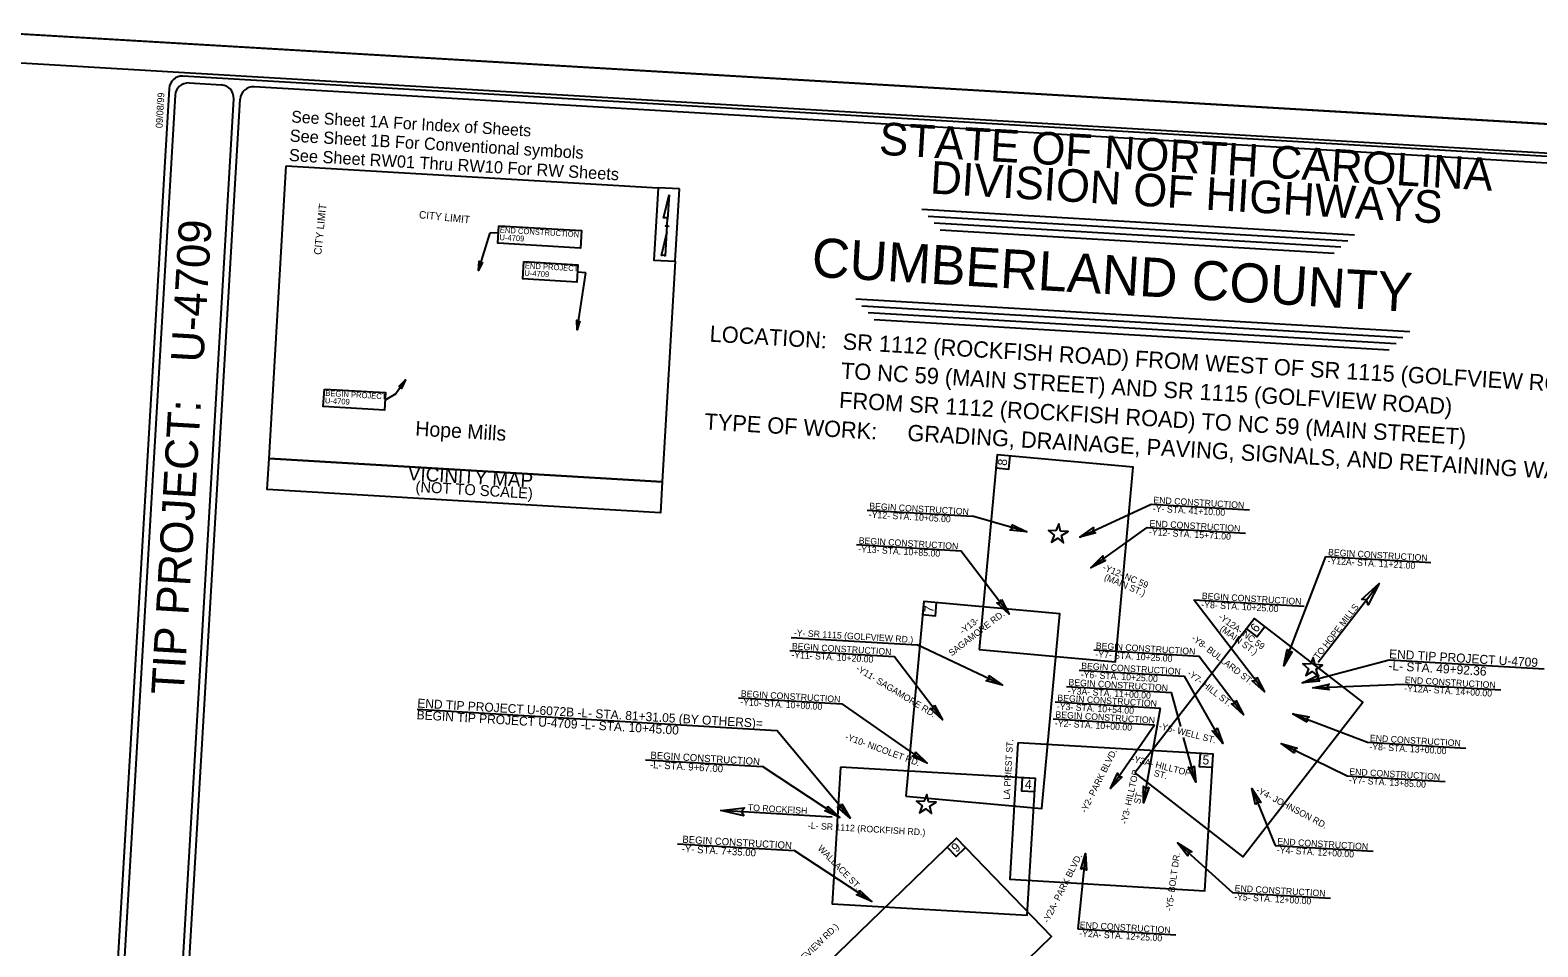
# Model space of a CAD drawing. Extents: x 1998567 to 2027801, y 439108 to 451079.
# Drawn here: x 2004989 to 2016563, y 444042 to 451079 of the extents above; entities that cross this region are included whole.
import ezdxf

# ---------------------------------------------------------------- set-up
doc = ezdxf.new("R2010")
doc.units = 0
for name, color, linetype in [('Default', 7, 'Continuous'), ('Old_Level_1', 7, 'Continuous'), ('Old_Level_12', 7, 'Continuous'), ('Old_Level_2', 7, 'Continuous'), ('Old_Level_63', 7, 'Continuous'), ('Prop Dimension', 7, 'Continuous'), ('Prop DSN Text', 7, 'Continuous'), ('Prop Grid Mask', 7, 'Continuous'), ('Prop RDY Traffic Signal CELL', 7, 'Continuous'), ('Prop Terminator CELL', 7, 'Continuous'), ('Sheet Cutting Line CELL', 7, 'Continuous'), ('Sheet Data Field CELL', 7, 'Continuous'), ('Sheet Plot Border Inside CELL', 7, 'Continuous'), ('Sheet Plot Border Outside CELL', 7, 'Continuous'), ('Sheet Title CELL', 7, 'Continuous'), ('Sheet Title Data Points CELL', 7, 'Continuous')]:
    doc.layers.add(name, color=color, linetype=linetype)

msp = doc.modelspace()

# ---------------------------------------------------------------- linework, layer by layer
at = {"layer": 'Old_Level_1'}
for points in [[(2006955, 450038), (2009810, 449870), (2009777, 449314), (2009941, 449305), (2009842, 447612), (2006823, 447790)], [(2009974, 449860), (2009810, 449870), (2009777, 449314), (2009941, 449305)], [(2012275, 446325), (2013321, 446229), (2013458, 447723), (2012413, 447819)], [(2006823, 447790), (2009842, 447612), (2009828, 447374), (2006809, 447552)], [(2011711, 445199), (2012757, 445103), (2012894, 446597), (2011849, 446693)], [(2013470, 445377), (2014300, 444733), (2015219, 445919), (2014389, 446562)], [(2012572, 445608), (2012510, 444560), (2014008, 444471), (2014070, 445520)], [(2011209, 445421), (2011147, 444373), (2012644, 444285), (2012706, 445333)], [(2011023, 443831), (2011754, 443077), (2012831, 444121), (2012100, 444875)]]:
    msp.add_lwpolyline(points, close=True, dxfattribs=at)
for points in [[(2012413, 447819), (2012403, 447719), (2012503, 447710), (2012512, 447810)], [(2011849, 446693), (2011840, 446593), (2011939, 446584), (2011948, 446684)], [(2014389, 446562), (2014328, 446483), (2014407, 446422), (2014468, 446501)], [(2014070, 445520), (2013970, 445525), (2013964, 445426), (2014064, 445420)], [(2012706, 445333), (2012606, 445339), (2012600, 445239), (2012700, 445233)], [(2012100, 444875), (2012028, 444806), (2012098, 444734), (2012170, 444803)]]:
    msp.add_lwpolyline(points, dxfattribs=at)
at = {"layer": 'Old_Level_2'}
for p, q in [((2009851, 449635), (2009894, 449815)), ((2009894, 449815), (2009883, 449627)), ((2009894, 449815), (2009894, 449815)), ((2009894, 449815), (2009894, 449815)), ((2009864, 449576), (2009896, 449574)), ((2009878, 449575), (2009864, 449576)), ((2009864, 449576), (2009864, 449576)), ((2009877, 449530), (2009883, 449633)), ((2009883, 449627), (2009883, 449633)), ((2009877, 449530), (2009833, 449346)), ((2009866, 449345), (2009877, 449530))]:
    msp.add_line(p, q, dxfattribs=at)
for centre, start_param, end_param in [((2009867, 449632), 0.216388, 2.908219), ((2009850, 449344), 0.201328, 3.141593)]:
    msp.add_ellipse(centre, major_axis=(16.6, -1.1), ratio=0.461098, start_param=start_param, end_param=end_param, dxfattribs=at)
at = {"layer": 'Old_Level_63'}
msp.add_line((2011237, 444988), (2011237, 444988), dxfattribs=at)
at = {"layer": 'Prop Dimension'}
for p, q in [((2011415, 447395), (2012223, 447347)), ((2012640, 447228), (2012223, 447347)), ((2013047, 447187), (2013596, 447440)), ((2013596, 447440), (2014349, 447396)), ((2013133, 446952), (2013565, 447261)), ((2013565, 447261), (2014318, 447217)), ((2011334, 447130), (2012135, 447082)), ((2012505, 446595), (2012135, 447082)), ((2014613, 446199), (2014936, 447039)), ((2014936, 447039), (2015743, 446992)), ((2013923, 446706), (2014769, 446657)), ((2014464, 445999), (2013923, 446706)), ((2010831, 446417), (2011798, 446360)), ((2010821, 446318), (2011622, 446271)), ((2012453, 446051), (2011798, 446360)), ((2013154, 446321), (2013962, 446274)), ((2011992, 445784), (2011622, 446271)), ((2014305, 445822), (2013962, 446274)), ((2014754, 446069), (2015423, 446245)), ((2015423, 446245), (2016613, 446175)), ((2013042, 446167), (2013850, 446120)), ((2014145, 445602), (2013850, 446120)), ((2010428, 445954), (2011223, 445908)), ((2012944, 446041), (2013752, 445993)), ((2013822, 445732), (2013752, 445993)), ((2014836, 446031), (2015525, 446059)), ((2015525, 446059), (2016279, 446015)), ((2007960, 445866), (2010722, 445703)), ((2011876, 445451), (2011223, 445908)), ((2012859, 445922), (2013667, 445874)), ((2013536, 445147), (2013667, 445874)), ((2012844, 445793), (2013621, 445747)), ((2013284, 445257), (2013621, 445747)), ((2014682, 445831), (2015257, 445613)), ((2011284, 445030), (2010722, 445703)), ((2013937, 445305), (2013844, 445649)), ((2014592, 445604), (2015100, 445355)), ((2015257, 445613), (2016010, 445568)), ((2009713, 445478), (2010611, 445425)), ((2011206, 445035), (2010611, 445425)), ((2014369, 445257), (2014547, 444820)), ((2015100, 445355), (2015853, 445311)), ((2009958, 444833), (2010855, 444780)), ((2013798, 444839), (2014220, 444460)), ((2014547, 444820), (2015300, 444775)), ((2011451, 444389), (2010855, 444780)), ((2013090, 444758), (2013031, 444179)), ((2014220, 444460), (2014973, 444416)), ((2013031, 444179), (2013784, 444134))]:
    msp.add_line(p, q, dxfattribs=at)
at = {"layer": 'Prop DSN Text'}
for p, q in [((2008430, 449233), (2008521, 449523)), ((2008584, 449520), (2008521, 449523)), ((2009189, 448778), (2009255, 449217)), ((2009255, 449217), (2009192, 449221)), ((2007871, 448396), (2007797, 448288)), ((2007797, 448288), (2007715, 448239)), ((2014877, 446226), (2015346, 446831)), ((2011147, 445038), (2010291, 445089))]:
    msp.add_line(p, q, dxfattribs=at)
at = {"layer": 'Prop Grid Mask'}
for points in [[(2008588, 449577), (2009221, 449540), (2009213, 449406), (2008580, 449443)], [(2008780, 449303), (2009195, 449278), (2009187, 449144), (2008772, 449169)], [(2007248, 448324), (2007718, 448297), (2007710, 448161), (2007240, 448189)]]:
    msp.add_lwpolyline(points, close=True, dxfattribs=at)
at = {"layer": 'Prop RDY Traffic Signal CELL'}
for points in [[(2012864, 447235), (2012806, 447239), (2012851, 447202), (2012830, 447148), (2012878, 447179), (2012923, 447143), (2012908, 447199), (2012957, 447230), (2012899, 447233), (2012885, 447289), (2012864, 447235)], [(2014817, 446211), (2014760, 446214), (2014804, 446177), (2014783, 446124), (2014832, 446155), (2014876, 446118), (2014862, 446174), (2014910, 446205), (2014853, 446209), (2014838, 446264), (2014817, 446211)], [(2011851, 445158), (2011793, 445161), (2011838, 445125), (2011817, 445071), (2011866, 445102), (2011910, 445065), (2011896, 445121), (2011944, 445152), (2011887, 445156), (2011872, 445212), (2011851, 445158)]]:
    msp.add_lwpolyline(points, dxfattribs=at)
at = {"layer": 'Prop Terminator CELL'}
for points in [[(2008462, 449299), (2008430, 449233), (2008437, 449307), (2008447, 449294)], [(2009210, 448848), (2009189, 448778), (2009185, 448852), (2009196, 448841)], [(2007820, 448343), (2007871, 448396), (2007840, 448329), (2007835, 448344)], [(2012526, 447283), (2012640, 447228), (2012513, 447241), (2012534, 447258)], [(2013171, 447220), (2013047, 447187), (2013153, 447261), (2013148, 447234)], [(2013248, 447007), (2013133, 446952), (2013223, 447043), (2013223, 447016)], [(2015211, 446707), (2015346, 446831), (2015260, 446668), (2015249, 446706)], [(2012447, 446708), (2012505, 446595), (2012411, 446682), (2012439, 446683)], [(2014678, 446308), (2014613, 446199), (2014638, 446324), (2014653, 446301)], [(2012349, 446124), (2012453, 446051), (2012329, 446084), (2012353, 446098)], [(2014405, 446112), (2014464, 445999), (2014370, 446085), (2014397, 446086)], [(2014891, 446081), (2014754, 446069), (2014880, 446127), (2014869, 446100)], [(2014963, 446015), (2014836, 446031), (2014962, 446059), (2014947, 446036)], [(2011933, 445897), (2011992, 445784), (2011898, 445871), (2011925, 445871)], [(2014246, 445935), (2014305, 445822), (2014211, 445908), (2014239, 445909)], [(2014101, 445722), (2014145, 445602), (2014063, 445701), (2014090, 445698)], [(2014792, 445766), (2014682, 445831), (2014808, 445807), (2014785, 445792)], [(2014695, 445529), (2014592, 445604), (2014715, 445568), (2014691, 445555)], [(2011786, 445540), (2011876, 445451), (2011760, 445505), (2011786, 445514)], [(2013373, 445348), (2013284, 445257), (2013337, 445374), (2013346, 445348)], [(2013925, 445431), (2013937, 445305), (2013882, 445421), (2013908, 445411)], [(2013580, 445267), (2013536, 445147), (2013536, 445275), (2013555, 445256)], [(2014396, 445133), (2014369, 445257), (2014437, 445149), (2014411, 445155)], [(2011220, 445140), (2011284, 445030), (2011186, 445113), (2011214, 445115)], [(2010469, 445047), (2010291, 445089), (2010474, 445110), (2010449, 445079)], [(2011113, 445122), (2011206, 445035), (2011089, 445085), (2011114, 445095)], [(2013877, 444739), (2013798, 444839), (2013907, 444771), (2013880, 444765)], [(2013056, 444636), (2013090, 444758), (2013099, 444631), (2013079, 444649)], [(2011357, 444476), (2011451, 444389), (2011333, 444440), (2011358, 444450)]]:
    msp.add_lwpolyline(points, close=True, dxfattribs=at)
at = {"layer": 'Sheet Cutting Line CELL'}
msp.add_line((2004409, 451079), (2021220, 450088), dxfattribs=at)
at = {"layer": 'Sheet Plot Border Inside CELL'}
msp.add_lwpolyline([(2003905, 440315), (2020541, 439334), (2021162, 449867), (2004526, 450848)], close=True, dxfattribs=at)
at = {"layer": 'Sheet Plot Border Outside CELL'}
msp.add_lwpolyline([(2021220, 450088), (2004409, 451079), (2003762, 440099), (2020573, 439108)], close=True, dxfattribs=at)
at = {"layer": 'Sheet Title CELL'}
for p, q in [((2005952, 440370), (2006552, 450552)), ((2006111, 442214), (2006602, 450550)), ((2011835, 449705), (2015157, 449509)), ((2011882, 449652), (2015104, 449462)), ((2011929, 449599), (2015051, 449415)), ((2011976, 449546), (2014999, 449368)), ((2011328, 449017), (2015580, 448767)), ((2011375, 448964), (2015527, 448720)), ((2011422, 448911), (2015475, 448673)), ((2011469, 448859), (2015422, 448626))]:
    msp.add_line(p, q, dxfattribs=at)
for points in [[(2020936, 449855), (2006162, 450726)], [(2006056, 450632), (2005450, 440350)], [(2006056, 450632), (2005450, 440350)], [(2006103, 450579), (2005503, 440397)], [(2006458, 450658), (2006209, 450673)], [(2020883, 449808), (2006708, 450643)]]:
    msp.add_lwpolyline(points, dxfattribs=at)
for centre, start, end in [((2006156, 450626), 86.6264, 176.6264), ((2006203, 450574), 86.6264, 176.6264), ((2006452, 450559), 356.6264, 86.6264), ((2006702, 450544), 86.6264, 176.6264)]:
    msp.add_arc(centre, 100, start, end, dxfattribs=at)
at = {"layer": 'Sheet Title Data Points CELL'}
for p, q in [((2013478, 449040), (2013478, 449040)), ((2014645, 448426), (2014645, 448426))]:
    msp.add_line(p, q, dxfattribs=at)

# ---------------------------------------------------------------- texts
at = {"layer": 'Default'}
msp.add_text('Hope Mills', height=111.8, rotation=356.6264, dxfattribs=at).set_placement((2007944, 447967))
at = {"layer": 'Old_Level_1'}
for s, height, rotation, p in [('CITY LIMIT', 57.5, 84.0488, (2007224, 449352)), ('CITY LIMIT', 57.5, 354.0488, (2007972, 449636)), ('VICINITY MAP', 107.85, 356.6263, (2007887, 447625)), ('(NOT TO SCALE)', 84.26, 356.6264, (2007946, 447534)), ('-Y12- NC 59 ', 50, 337.0809, (2013218, 446937)), ('(MAIN ST.)', 50, 337.0809, (2013230, 446861)), (' SAGAMORE RD.', 50, 37.6982, (2012049, 446259)), ('-Y13-', 50, 37.6982, (2012149, 446439)), ('-Y12A- NC 59', 50, 324.1244, (2014107, 446564)), ('-Y8- BULLARD ST.', 50, 322.4598, (2013901, 446401)), ('(MAIN ST.)', 50, 324.1244, (2014118, 446474)), ('-Y11- SAGAMORE RD.', 50, 328.8004, (2011324, 446165)), ('-Y7- HILL ST.', 50, 322.4598, (2013868, 446132)), ('-Y6- WELL ST.', 50, 345.5311, (2013651, 445715)), ('-Y10- NICOLET RD.', 50, 339.8061, (2011242, 445636)), ('LA PRIEST ST.', 50, 86.6264, (2012509, 445171)), ('-Y2- PARK BLVD. ', 50, 63.4557, (2013094, 445065)), ('-Y3A- HILLTOP', 50, 345.6554, (2013440, 445465)), ('-Y3- HILLTOP', 50, 77.3731, (2013409, 444981)), ('ST.', 50, 345.6554, (2013612, 445354)), ('-Y4- JOHNSON RD.', 50, 332.1794, (2014395, 445229)), ('ST.', 50, 77.3731, (2013510, 445135)), ('-L- SR 1112 (ROCKFISH RD.)', 50, 356.6264, (2010959, 444949)), ('WALLACE ST.', 50, 314.169, (2011031, 444793)), ('-Y2A- PARK BLVD. ', 50, 63.4557, (2012806, 444220)), ('-Y5- BOLT DR.', 50, 82.1647, (2013755, 444314))]:
    msp.add_text(s, height=height, rotation=rotation, dxfattribs=at).set_placement(p)
at = {"layer": 'Old_Level_12'}
for s, p in [('See Sheet 1B For Conventional symbols', (2006980, 450224)), ('See Sheet RW01 Thru RW10 For RW Sheets', (2006974, 450075))]:
    msp.add_text(s, height=93.81, rotation=356.6266, dxfattribs=at).set_placement(p)
at = {"layer": 'Prop DSN Text'}
for s, height, rotation, p in [('END CONSTRUCTION', 43.61, 356.6264, (2008594, 449525)), ('U-4709', 43.6, 356.6264, (2008591, 449468)), ('U-4709', 43.6, 356.6264, (2008782, 449194)), ('END PROJECT', 43.61, 356.6264, (2008786, 449251)), ('BEGIN PROJECT', 43.61, 356.6264, (2007254, 448272)), ('U-4709', 43.6, 356.6264, (2007251, 448215)), ('8', 70, 84.7467, (2012486, 447733)), ('END CONSTRUCTION', 50, 356.6264, (2013611, 447448)), ('-Y12- STA. 10+05.00', 50, 356.6264, (2011426, 447337)), ('BEGIN CONSTRUCTION', 50, 356.6264, (2011430, 447402)), ('-Y- STA. 41+10.00', 50, 356.6264, (2013607, 447383)), ('-Y12- STA. 15+71.00', 50, 356.6264, (2013577, 447203)), ('END CONSTRUCTION', 50, 356.6264, (2013581, 447269)), ('-Y13- STA. 10+85.00', 50, 356.6264, (2011345, 447072)), ('BEGIN CONSTRUCTION', 50, 356.6264, (2011349, 447137)), ('-Y12A- STA. 11+21.00', 50, 356.6264, (2014948, 446982)), ('BEGIN CONSTRUCTION', 50, 356.6264, (2014952, 447047)), ('BEGIN CONSTRUCTION', 50, 356.6264, (2013983, 446712)), ('7', 70, 84.7467, (2011923, 446605)), ('-Y8- STA. 10+25.00', 50, 356.6264, (2013979, 446646)), ('TO HOPE MILLS', 50, 52.2051, (2014878, 446245)), ('6', 70, 52.2051, (2014405, 446450)), ('-Y- SR 1115 (GOLFVIEW RD.)', 50, 356.6264, (2010851, 446429)), ('-Y11- STA. 10+20.00', 50, 356.6264, (2010832, 446260)), ('BEGIN CONSTRUCTION', 50, 356.6264, (2010836, 446326)), ('-Y7- STA. 10+25.00', 50, 356.6264, (2013165, 446264)), ('BEGIN CONSTRUCTION', 50, 356.6264, (2013169, 446329)), ('END TIP PROJECT U-4709', 68.75, 356.6264, (2015420, 446257)), ('BEGIN CONSTRUCTION', 50, 356.6264, (2013057, 446175)), ('-L- STA. 49+92.36', 68.75, 356.6264, (2015415, 446167)), ('BEGIN CONSTRUCTION', 50, 356.6264, (2012959, 446049)), ('-Y6- STA. 10+25.00', 50, 356.6264, (2013053, 446109)), ('END CONSTRUCTION', 50, 356.6264, (2015541, 446067)), ('BEGIN CONSTRUCTION', 50, 356.6264, (2010444, 445962)), ('BEGIN CONSTRUCTION', 50, 356.6264, (2012874, 445929)), ('-Y3A- STA. 11+00.00', 50, 356.6264, (2012955, 445983)), ('-Y12A- STA. 14+00.00', 50, 356.6264, (2015537, 446002)), ('BEGIN TIP PROJECT U-4709 -L- STA. 10+45.00', 68.75, 356.6264, (2007955, 445789)), ('END TIP PROJECT U-6072B -L- STA. 81+31.05 (BY OTHERS)=', 68.75, 356.6264, (2007960, 445879)), ('-Y10- STA. 10+00.00', 50, 356.6264, (2010440, 445897)), ('BEGIN CONSTRUCTION', 50, 356.6264, (2012859, 445801)), ('-Y3- STA. 10+54.00', 50, 356.6264, (2012870, 445864)), ('-Y2- STA. 10+00.00', 50, 356.6264, (2012855, 445735)), ('-Y8- STA. 13+00.00', 50, 356.6264, (2015269, 445555)), ('END CONSTRUCTION', 50, 356.6264, (2015273, 445621)), ('BEGIN CONSTRUCTION', 55, 356.6264, (2009750, 445486)), ('5', 70, 356.6264, (2013987, 445443)), ('-L- STA. 9+67.00', 55, 356.6264, (2009746, 445414)), ('END CONSTRUCTION', 50, 356.6264, (2015115, 445363)), ('4', 70, 356.6264, (2012624, 445256)), ('-Y7- STA. 13+85.00', 50, 356.6264, (2015111, 445298)), ('TO ROCKFISH', 50, 356.7538, (2010498, 445087)), ('-Y- STA. 7+35.00', 55, 356.6264, (2009990, 444769)), ('BEGIN CONSTRUCTION', 55, 356.6264, (2009995, 444841)), ('9', 70, 44.1168, (2012101, 444762)), ('-Y4- STA. 12+00.00', 50, 356.6264, (2014559, 444762)), ('END CONSTRUCTION', 50, 356.6264, (2014562, 444827)), ('-Y5- STA. 12+00.00', 50, 356.6264, (2014231, 444402)), ('END CONSTRUCTION', 50, 356.6264, (2014235, 444468)), ('-Y- SR 1115 (GOLFVIEW RD.)', 50, 44.1995, (2010543, 443551)), ('END CONSTRUCTION', 50, 356.6264, (2013046, 444186)), ('-Y2A- STA. 12+25.00', 50, 356.6264, (2013042, 444121))]:
    msp.add_text(s, height=height, rotation=rotation, dxfattribs=at).set_placement(p)
at = {"layer": 'Sheet Data Field CELL'}
for s, height, p in [('CUMBERLAND COUNTY', 300, (2010984, 449187)), ('SR 1112 (ROCKFISH ROAD) FROM WEST OF SR 1115 (GOLFVIEW ROAD)', 125, (2011224, 448628)), ('TO NC 59 (MAIN STREET) AND SR 1115 (GOLFVIEW ROAD)', 125, (2011211, 448404)), ('FROM SR 1112 (ROCKFISH ROAD) TO NC 59 (MAIN STREET)', 125, (2011197, 448179)), ('GRADING, DRAINAGE, PAVING, SIGNALS, AND RETAINING WALL.', 125, (2011721, 447927))]:
    msp.add_text(s, height=height, rotation=356.6264, dxfattribs=at).set_placement(p)
at = {"layer": 'Sheet Title CELL'}
for s, height, rotation, p in [('09/08/99', 52.5, 86.6264, (2006005, 450326)), ('See Sheet 1A For Index of Sheets', 90.86, 356.6264, (2006992, 450371)), ('STATE OF NORTH CAROLINA', 250, 356.6264, (2011502, 450124)), ('DIVISION OF HIGHWAYS', 250, 356.6264, (2011894, 449826)), ('U-4709  ', 250, 86.6264, (2006319, 448523)), ('LOCATION: ', 125, 356.6264, (2010203, 448688)), ('TIP PROJECT:', 250, 86.6264, (2006168, 445972)), ('TYPE OF WORK:', 125, 356.6264, (2010163, 448014))]:
    msp.add_text(s, height=height, rotation=rotation, dxfattribs=at).set_placement(p)

doc.saveas('drawing.dxf')
